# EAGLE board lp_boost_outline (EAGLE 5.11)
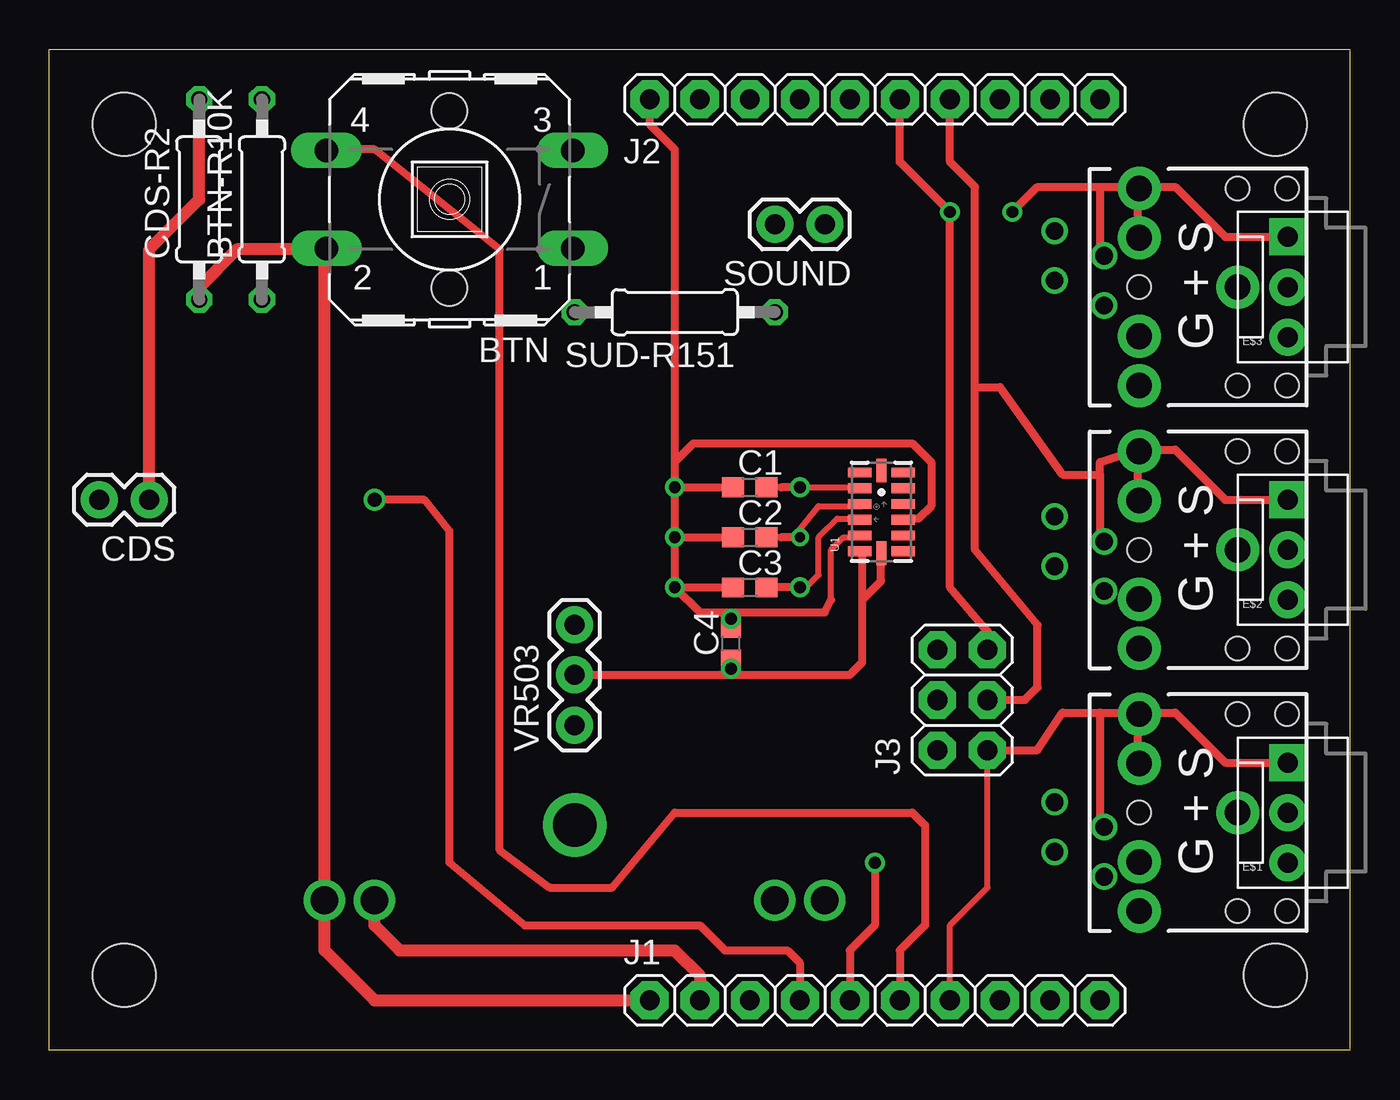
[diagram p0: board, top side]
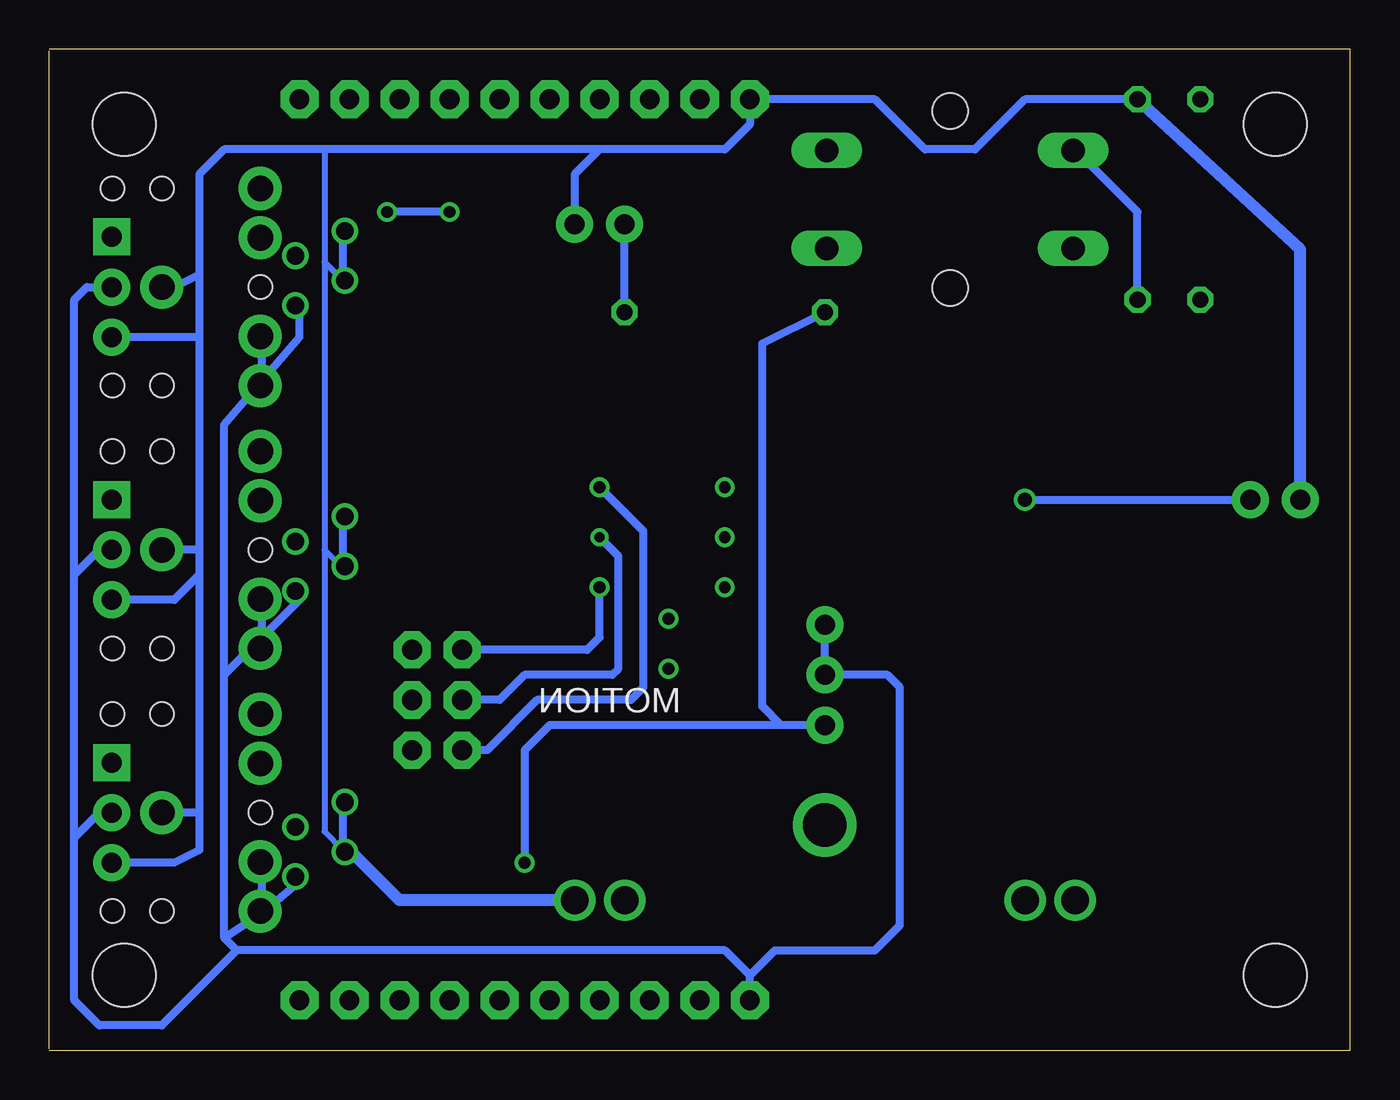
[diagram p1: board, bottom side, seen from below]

Size 66.04 x 50.8 mm. Coordinates in mm from the lower left corner, seen from the top.
Outline: 66.04,0.08 66.04,50.72
Outline: 66.04,0 0,0 0,50.8 66.04,50.8
Copper layers (1*16): Top 0.035mm / dielectric 1.5mm / Bottom 0.035mm
Design rules "default": minimum track width 10mil, minimum drill 24mil, track to track 8mil, track to pad 8mil, pad to pad 8mil, via to via 8mil, smd to smd 8mil, copper to edge 40mil, drill to drill 8mil, minimum pad ring 10mil, minimum via ring 8mil, stop-mask expansion 4mil, vias tented up to drill 0mil, thermal gap 10mil
Holes 3.2 mm at 62.23,46.99 62.23,3.81 3.81,46.99 3.81,3.81

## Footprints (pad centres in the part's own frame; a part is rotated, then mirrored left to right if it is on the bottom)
B3F-40XX = drill 1.194 long: 1 -6.248,2.489; 2 6.248,2.489; 3 -6.248,-2.489; 4 6.248,-2.489 | hole 1.803: 0,-4.496; 0,4.496
0207/10 = drill 0.813 octagon: 1 -5.08,0; 2 5.08,0
C0603 = smd 1.1 x 1: 1 -0.85,0; 2 0.85,0
1X02 = drill 1.016 pad 1.88 round: 1 0,0; 2 2.54,0
MOLEX-1X3 = drill 1.016 pad 1.88 square: 1 0,0 | drill 1.016 pad 1.88 round: 2 2.54,0; 3 5.08,0
AUDIO-JACK = drill 1.3 pad 2.184 round: RING 5,5; RSH 5,2.5; SLEEVE 0,0; TIP 5,-5; TSH 5,-2.5 | hole 1.2: 0,5; -2.5,5; -2.5,-5; 0,-5; 5,0
PH1X10OCT76 = drill 1 pad 1.93 octagon: 1 0,0; 2 2.54,0; 3 5.08,0; 4 7.62,0; 5 10.16,0; 6 12.7,0; 7 15.24,0; 8 17.78,0; 9 20.32,0; 10 22.86,0
2X03 = drill 1.016 pad 1.88 octagon: 1 -2.54,-1.27; 2 -2.54,1.27; 3 0,-1.27; 4 0,1.27; 5 2.54,-1.27; 6 2.54,1.27
LGA14 = smd 0.5 x 1.2: 1 2,1.1; 2 1.2,1.1; 3 0.4,1.1; 4 -0.4,1.1; 5 -1.2,1.1; 6 -2,1.1; 8 -2,-1.1; 9 -1.2,-1.1; 10 -0.4,-1.1; 11 0.4,-1.1; 12 1.2,-1.1; 13 2,-1.1 | smd 1.2 x 0.5: 7 -2.1,0; 14 2.1,0
1X03 = drill 1.016 pad 1.88 round: 1 0,0; 2 2.54,0; 3 5.08,0

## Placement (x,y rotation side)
BTN  [B3F-40XX]  20.32,43.18 180 top
BTN-R10K  [0207/10]  10.79,43.18 90 top
C1  [C0603]  35.56,28.57 0 top
C2  [C0603]  35.56,26.04 0 top
C3  [C0603]  35.56,23.5 0 top
C4  [C0603]  34.61,20.64 90 top
CDS  [1X02]  5.08,27.94 180 top
CDS-R2  [0207/10]  7.62,43.18 90 top
CON-A  [MOLEX-1X3]  62.87,14.61 270 top
CON-B  [MOLEX-1X3]  62.87,27.94 270 top
CON-C  [MOLEX-1X3]  62.87,41.27 270 top
E$1  [AUDIO-JACK]  60.33,12.06 180 top
E$2  [AUDIO-JACK]  60.33,25.4 180 top
E$3  [AUDIO-JACK]  60.33,38.73 180 top
J1  [PH1X10OCT76]  30.48,2.54 0 top
J2  [PH1X10OCT76]  30.48,48.26 0 top
J3  [2X03]  46.35,17.78 90 top
SOUND  [1X02]  39.37,41.91 180 top
SUD-R151  [0207/10]  31.75,37.47 180 top
U1  [LGA14]  42.24,27.32 90 top
VR503  [1X03]  26.67,16.51 90 top

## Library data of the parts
BTN = switch-omron; MF: OMRON COMPONENTS USA; MPN: B3F-4000; OC_FARNELL: 176434; OC_NEWARK: 36K3105
BTN-R10K CDS-R2 SUD-R151 = resistor
C1-C4 = rcl
CDS CON-A CON-B CON-C E$1-E$3 J3 SOUND U1 VR503 = SparkFun
J1 J2 = MY_CONN

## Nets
!RST: J2.5
LIN: BTN-R10K.1
P1.0: J1.2
P1.1: J1.3
P1.3: J1.5 SUD-R151.2 VR503.1
P1.4: J1.6
P1.5: CON-A.1 J1.7
P1.6: CON-B.1 J2.7
P1.7: CON-C.1 J2.6
P2.0: J1.8
P2.1: J1.9
P2.2: J1.10
P2.3: J2.10
P2.4: J2.9
P2.5: J2.8
P2.6: J2.2
P2.7: J2.3
S$15: SOUND.2 SUD-R151.1
S$16: CDS-R2.2 CDS.1 J1.4
TEST: J2.4
V-: BTN-R10K.2 CDS.2 CON-A.3 CON-B.3 CON-C.3 E$1.SLEEVE E$2.SLEEVE E$3.SLEEVE J2.1 SOUND.1
VCC: CDS-R2.1 CON-A.2 CON-B.2 CON-C.2 J1.1 VR503.2 VR503.3

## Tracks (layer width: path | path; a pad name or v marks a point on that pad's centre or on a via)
LIN
  Bottom 0.406: BTN-R10K.1 10.79,42.55 13.97,45.72
N$3  (via drill 2.2)
  other vias: 26.67,11.43
N$5  (via drill 1.4)
  Bottom 0.61: v39.37,7.62 48.26,7.62 50.8,10.16
P1.0  (via drill 1.4)
  Top 0.61: v16.51,7.62 16.51,6.35 17.78,5.08 31.75,5.08 33.02,3.81 J1.2
P1.3  (via drill 0.6)
  Top 0.406: v41.91,9.53 41.91,6.35 40.64,5.08 J1.5
  Bottom 0.406: SUD-R151.2 29.84,35.88 29.84,17.46 28.89,16.51 | 28.89,16.51 40.64,16.51 41.91,15.24 v41.91,9.53 | VR503.1 28.89,16.51
P1.4
  Top 0.406: 13.97,45.72 16.51,45.72 22.86,40.64 22.86,10.16 25.4,8.26 28.57,8.26 31.75,12.06 43.81,12.06 44.45,11.43 44.45,6.35 43.18,5.08 J1.6
P1.5
  Top 0.305: J1.7 45.72,6.35 47.62,8.26 47.62,15.24
  Top 0.406: CON-A.1 59.69,14.61 57.15,17.14 55.24,17.14 | 55.24,17.14 55.24,15.24 | 53.34,17.14 55.24,17.14 | 53.34,17.14 51.44,17.14 50.16,15.24 47.62,15.24 | 53.34,17.14 53.34,11.43
P1.6
  Top 0.406: J2.7 45.72,45.09 46.99,43.81 46.99,33.66 | 46.99,33.66 46.99,25.4 50.16,21.59 50.16,18.41 49.53,17.78 47.62,17.78 | CON-B.1 59.69,27.94 57.15,30.48 55.24,30.48 | 55.24,30.48 55.24,28.57 | 55.24,30.48 53.34,29.84 53.34,29.21 | 53.34,29.21 53.34,26.04 | 53.34,29.21 51.44,29.21 48.26,33.66 46.99,33.66
P1.7  (via drill 0.6)
  Top 0.406: CON-C.1 59.69,41.27 57.15,43.81 55.24,43.81 | 55.24,43.81 55.24,41.91 | 53.34,43.81 55.24,43.81 | 53.34,43.81 53.34,40.01 | v48.9,42.55 50.16,43.81 53.34,43.81 | J2.6 43.18,45.09 v45.72,42.55 45.72,23.5 47.62,21.27 47.62,20.32
  Bottom 0.406: v45.72,42.55 v48.9,42.55
S$1  (via drill 0.9)
  other vias: 51.03,27.09
S$2  (via drill 0.9)
  other vias: 51.03,24.57
S$3  (via drill 0.6)
  other vias: 34.61,21.91
S$4  (via drill 0.9)
  other vias: 53.55,23.3
S$5  (via drill 0.9)
  other vias: 53.55,25.82
S$6  (via drill 0.6)
  Top 0.305: 38.42,23.5 39.05,24.13 39.05,26.04 40.01,26.99 40.64,26.99
  Top 0.406: 38.42,23.5 v38.1,23.5 36.83,23.5
  Bottom 0.406: v38.1,23.5 38.1,20.95 38.73,20.32 45.09,20.32
S$7  (via drill 0.6)
  other vias: 34.61,19.37
S$8  (via drill 0.9)
  other vias: 51.03,39.06
S$9  (via drill 0.9)
  other vias: 51.03,41.58
S$10
  Bottom 0.406: 51.12,10.16 51.12,12.7
S$11  (via drill 0.9)
  other vias: 53.55,40.32
S$12  (via drill 0.9)
  other vias: 53.55,37.8
S$13  (via drill 0.9)
  other vias: 51.03,12.6
S$14  (via drill 0.9)
  other vias: 51.03,10.07
S$15
  Bottom 0.406: SUD-R151.1 SOUND.2
S$16  (via drill 0.7)
  Top 0.406: J1.4 38.1,4.45 37.47,5.08 34.29,5.08 33.02,6.35 24.13,6.35 20.32,9.53 20.32,26.35 19.05,27.94 v16.51,27.94
  Top 0.61: CDS-R2.2 7.62,43.18 5.08,40.64 CDS.1
  Bottom 0.406: v16.51,27.94 CDS.1
S$17  (via drill 0.9)
  other vias: 53.55,11.34
S$18  (via drill 0.9)
  other vias: 53.55,8.81
S$19  (via drill 0.6)
  Top 0.305: 38.42,28.57 40.64,28.57 | 37.15,28.57 36.83,28.57
  Top 0.406: 37.15,28.57 v38.1,28.57 38.42,28.57
  Bottom 0.406: v38.1,28.57 35.88,26.35 35.88,18.41 36.51,17.78 41.27,17.78 43.81,15.24 45.4,15.24
S$20  (via drill 0.5)
  Top 0.305: 41.27,27.62 39.05,27.62 37.78,26.04 | 37.15,26.04 36.83,26.04
  Top 0.406: 37.15,26.04 37.78,26.04 v38.1,26.04
  Bottom 0.406: v38.1,26.04 37.15,25.08 37.15,19.37 37.47,19.05 41.91,19.05 43.18,17.78 45.09,17.78
S$25  (via drill 1.4)
  other vias: 36.83,7.62
V-  (via drill 0.6)
  Top 0.305: 39.69,22.86 39.69,25.4 40.32,26.04 40.96,26.04
  Top 0.406: J2.1 30.48,46.99 31.75,45.72 31.75,29.84 | 31.75,29.84 v31.75,28.57 | v31.75,28.57 34.29,28.57 | v31.75,28.57 v31.75,26.04 | v31.75,26.04 34.29,26.04 | v31.75,26.04 v31.75,23.5 | v31.75,23.5 34.29,23.5 | v31.75,23.5 33.02,22.23 39.37,22.23 39.69,22.86 | 43.81,26.99 44.13,26.99 44.77,27.62 44.77,29.84 43.81,30.8 32.7,30.8 31.75,29.84
  Bottom 0.305: 51.12,10.16 52.07,11.11 52.07,25.4 | 52.07,25.4 51.12,24.45 | 52.07,40.01 51.12,39.05 | 52.07,40.01 52.07,25.4 | 52.07,45.72 52.07,40.01
  Bottom 0.406: CON-A.3 59.69,9.53 58.42,10.16 58.42,12.06 | 58.42,12.06 E$1.SLEEVE | CON-B.3 59.69,22.86 58.42,24.13 | 58.42,24.13 58.42,12.06 | 58.42,25.4 58.42,24.13 | 58.42,25.4 E$2.SLEEVE | E$3.SLEEVE 59.69,38.73 58.42,39.37 | 58.42,36.2 58.42,25.4 | 58.42,36.2 CON-C.3 | 58.42,39.37 58.42,36.2 | 58.42,39.37 58.42,44.45 57.15,45.72 52.07,45.72 38.1,45.72 | SOUND.1 39.37,44.45 38.1,45.72 | 38.1,45.72 31.75,45.72 30.48,46.99 J2.1 24.13,48.26 21.59,45.72 19.05,45.72 16.51,48.26 BTN-R10K.2 | 51.12,24.45 51.12,26.99 | 51.12,39.05 51.12,41.59
  Bottom 0.61: BTN-R10K.2 2.54,40.64 CDS.2
VCC  (via drill 1.4)
  Top 0.406: 41.27,22.86 41.27,19.68 40.64,19.05 VR503.2 | 41.27,22.86 41.27,25.08 | 42.23,24.77 42.23,23.81 41.27,22.86
  Top 0.61: CDS-R2.1 7.62,38.73 9.53,40.64 13.97,40.64 v13.97,7.62 13.97,5.08 16.51,2.54 J1.1
  Bottom 0.406: CON-C.2 64.14,38.73 64.77,38.1 64.77,24.13 | 53.34,23.5 53.34,22.86 55.24,20.95 | 53.34,38.1 53.34,36.2 55.24,33.97 | CON-B.2 63.5,25.4 64.77,24.13 | CON-A.2 63.5,12.06 64.77,10.79 | 55.24,33.97 55.24,35.56 | 55.24,20.95 55.24,22.23 | 57.15,19.05 55.24,20.95 | 55.24,33.97 57.15,31.75 57.15,19.05 | 64.77,10.79 64.77,24.13 | 64.77,10.79 64.77,2.54 63.5,1.27 60.33,1.27 56.52,5.08 | 53.34,8.89 53.34,8.57 55.24,6.99 | 55.24,6.99 55.24,8.89 | 57.15,5.71 57.15,19.05 | 57.15,5.71 55.24,6.99 | 56.52,5.08 57.15,5.71 | 56.52,5.08 31.75,5.08 30.48,3.81 | 30.48,3.81 29.21,5.08 24.13,5.08 22.86,6.35 22.86,18.41 23.5,19.05 VR503.2 VR503.3 | J1.1 30.48,3.81

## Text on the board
tNames: G + S | G + S | G + S
bNames: MOTION
tDocu: C | X | Y | B | Z | A
bDocu: Scratch Booster Pack | MSP430 LaunchPad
